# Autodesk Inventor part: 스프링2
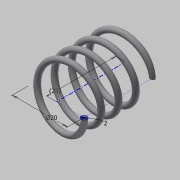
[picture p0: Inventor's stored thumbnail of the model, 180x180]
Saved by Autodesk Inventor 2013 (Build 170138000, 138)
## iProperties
Created: 2016-07
Part Number: 스프링2
Material: 일반
Document SubType Name: Modeling
Designer: dgall
Density: 1 g/cm^3
Author: dgall
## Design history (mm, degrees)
sketch "스케치1"
  geometry: L1 (0, 0)-(10, 0); L2 (10, 0)-(10, 22.5); L3 (10, 22.5)-(0, 22.5); L4 (0, 22.5)-(0, 0); C1 r 1 at (10, 0)
  constraints: 8 end point, 2 parallel, 1 centre point, 1 coincident, 1 horizontal, 1 perpendicular
  dimensions: "d0" = 2 diameter of C1; "d2" = 22.5 distance of L3.end L1.start (derived); "d3" = 20 diameter of L2 L4
feature "코일1" sketch "스케치1" pitch "d4" = 10; turns "d6" = 4; dims "d5" = 22.5 (= d2), "d7" = 0, angle "d8" = 90 deg, angle "d9" = 90 deg, "d10" = 0, "d11" = 0
feature "분할1"
node "작업 평면1"
feature "분할2"
node "솔리드1"
